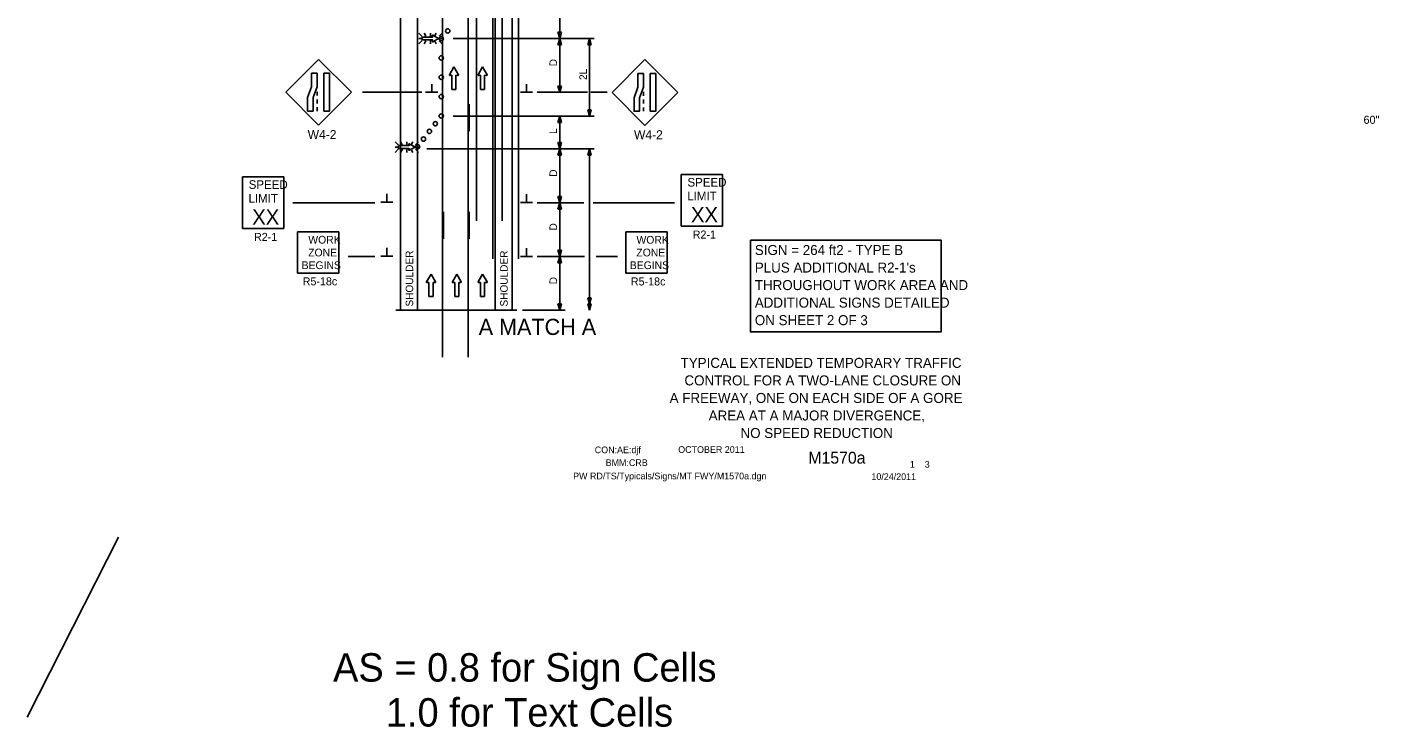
# Model space of a CAD drawing. Extents: x 16563 to 19504, y 6261 to 8279.
# Drawn here: x 16563 to 17820, y 6990 to 7640 of the extents above; entities that cross this region are included whole.
import ezdxf

# ---------------------------------------------------------------- set-up
doc = ezdxf.new("R2010")
doc.units = 0
for name, color, linetype in [('ALI_LEGAL_EX', 7, 'Continuous'), ('BORDER', 7, 'Continuous'), ('BORDER_SIGNAL_WO', 7, 'Continuous'), ('MT_SCRATCH_LEVEL_E', 7, 'Continuous'), ('PAVT_EDGE_EX', 7, 'Continuous'), ('TRAFFIC_SIGNS_PR', 7, 'Continuous'), ('TYPICAL_TEXT_DIMEN_EX', 7, 'Continuous'), ('TYPICAL_TEXT_DIMEN_PR', 7, 'Continuous')]:
    doc.layers.add(name, color=color, linetype=linetype)

msp = doc.modelspace()

# ---------------------------------------------------------------- linework, layer by layer
at = {"layer": 'ALI_LEGAL_EX'}
for p, q in [((16980.7, 8278.5), (16980.7, 7460.4)), ((17004.7, 8278.5), (17004.7, 7460.4)), ((16995.9, 8243.2), (16995.9, 7425)), ((17019.9, 8243.2), (17019.9, 7425)), ((16949, 7333.6), (16949, 7943.8)), ((16973, 7443.4), (16973, 7943.8)), ((16973, 7333.6), (16973, 7943.8)), ((16973, 7333.6), (16973, 7943.8))]:
    msp.add_line(p, q, dxfattribs=at)
for points in [[(16974, 7543.6), (16974, 7568.6)], [(16950, 7443.6), (16950, 7468.6)], [(16974, 7443.6), (16974, 7468.6)]]:
    msp.add_lwpolyline(points, dxfattribs=at)
at = {"layer": 'MT_SCRATCH_LEVEL_E'}
for p, q in [((16959.8, 7603.3), (16955.7, 7596)), ((16956.2, 7595.4), (16957.9, 7595.7)), ((16957.9, 7595.7), (16957.9, 7582.4)), ((16963.9, 7596), (16959.8, 7603.3)), ((16961.7, 7582.4), (16961.7, 7595.7)), ((16961.7, 7595.7), (16963.4, 7595.4)), ((16986.4, 7603.3), (16982.3, 7596)), ((16982.8, 7595.4), (16984.6, 7595.7)), ((16984.6, 7595.7), (16984.6, 7582.4)), ((16990.6, 7596), (16986.4, 7603.3)), ((16988.3, 7582.4), (16988.3, 7595.7)), ((16988.3, 7595.7), (16990.1, 7595.4)), ((16957.9, 7582.4), (16961.7, 7582.4)), ((16984.6, 7582.4), (16988.3, 7582.4)), ((16938.5, 7410.7), (16934.4, 7403.5)), ((16934.9, 7402.8), (16936.6, 7403.1)), ((16936.6, 7403.1), (16936.6, 7389.9)), ((16942.6, 7403.5), (16938.5, 7410.7)), ((16940.4, 7389.9), (16940.4, 7403.1)), ((16940.4, 7403.1), (16942.2, 7402.8)), ((16962.4, 7410.7), (16958.3, 7403.5)), ((16958.8, 7402.8), (16960.5, 7403.1)), ((16960.5, 7403.1), (16960.5, 7389.9)), ((16966.5, 7403.5), (16962.4, 7410.7)), ((16964.3, 7389.9), (16964.3, 7403.1)), ((16964.3, 7403.1), (16966.1, 7402.8)), ((16986.4, 7410.7), (16982.3, 7403.5)), ((16982.8, 7402.8), (16984.6, 7403.1)), ((16984.6, 7403.1), (16984.6, 7389.9)), ((16990.6, 7403.5), (16986.4, 7410.7)), ((16988.3, 7389.9), (16988.3, 7403.1)), ((16988.3, 7403.1), (16990.1, 7402.8)), ((16936.6, 7389.9), (16940.4, 7389.9)), ((16960.5, 7389.9), (16964.3, 7389.9)), ((16984.6, 7389.9), (16988.3, 7389.9))]:
    msp.add_line(p, q, dxfattribs=at)
for centre, start, end in [((16956.1, 7595.8), 150.4248, 279.9638), ((16963.5, 7595.8), 260.0362, 29.7731), ((16982.7, 7595.8), 150.4248, 279.9638), ((16990.2, 7595.8), 260.0362, 29.7731), ((16934.8, 7403.3), 150.4248, 279.9638), ((16942.2, 7403.3), 260.0362, 29.7731), ((16958.7, 7403.3), 150.4248, 279.9638), ((16966.1, 7403.3), 260.0362, 29.7731), ((16982.7, 7403.3), 150.4248, 279.9638), ((16990.2, 7403.3), 260.0362, 29.7731)]:
    msp.add_arc(centre, 0.463, start, end, dxfattribs=at)
at = {"layer": 'PAVT_EDGE_EX'}
for p, q in [((16910, 7753.8), (16910, 7377.1)), ((16926, 7753.8), (16926, 7377.1)), ((16998, 7753.8), (16998, 7377.1)), ((17014, 7753.8), (17014, 7377.1))]:
    msp.add_line(p, q, dxfattribs=at)
at = {"layer": 'TRAFFIC_SIGNS_PR'}
for p, q in [((16929.8, 7631.8), (16927, 7634.6)), ((16929.8, 7629.7), (16927, 7629.7)), ((16932.1, 7634.6), (16933.7, 7631.8)), ((16937.9, 7631.8), (16937.9, 7634.6)), ((16943.3, 7634.6), (16942.1, 7632.5)), ((16948.8, 7634.6), (16946, 7631.8)), ((16946, 7629.7), (16948.8, 7629.7)), ((16929.8, 7627.7), (16927, 7624.9)), ((16933.7, 7627.7), (16932.1, 7624.9)), ((16937.9, 7627.7), (16937.9, 7624.9)), ((16942.1, 7627.1), (16943.3, 7624.9)), ((16948.8, 7624.9), (16946, 7627.7)), ((16834, 7610.2), (16803.4, 7579.7)), ((16864.5, 7579.7), (16834, 7610.2)), ((17137.4, 7610.1), (17106.8, 7579.5)), ((17167.9, 7579.5), (17137.4, 7610.1)), ((16803.4, 7579.7), (16834, 7549.1)), ((16832.6, 7580.2), (16832.6, 7576.6)), ((16834, 7549.1), (16864.5, 7579.7)), ((17106.8, 7579.5), (17137.4, 7549)), ((17136, 7580.1), (17136, 7576.5)), ((17137.4, 7549), (17167.9, 7579.5)), ((16832.6, 7573), (16832.6, 7569.4)), ((17136, 7572.9), (17136, 7569.3)), ((16832.6, 7565.8), (16832.6, 7562.2)), ((17136, 7565.7), (17136, 7562.1)), ((16907.9, 7530.8), (16905.1, 7533.6)), ((16907.9, 7528.8), (16905.1, 7528.8)), ((16910.2, 7533.6), (16911.8, 7530.8)), ((16916, 7530.8), (16916, 7533.6)), ((16921.5, 7533.6), (16920.3, 7531.5)), ((16926.9, 7533.6), (16924.1, 7530.8)), ((16924.1, 7528.8), (16926.9, 7528.8)), ((16907.9, 7526.8), (16905.1, 7523.9)), ((16911.9, 7526.8), (16910.2, 7523.9)), ((16916, 7526.8), (16916, 7523.9)), ((16920.2, 7526.1), (16921.5, 7523.9)), ((16926.9, 7523.9), (16924.1, 7526.8)), ((16763.2, 7501.1), (16801.6, 7501.1)), ((16763.2, 7453.1), (16763.2, 7501.1)), ((16801.6, 7453.1), (16801.6, 7501.1)), ((17171.1, 7503.2), (17209.5, 7503.2)), ((17171.1, 7455.2), (17171.1, 7503.2)), ((17209.5, 7455.2), (17209.5, 7503.2)), ((17171.1, 7455.2), (17209.5, 7455.2)), ((16763.2, 7453.1), (16801.6, 7453.1)), ((16814.4, 7411.7), (16814.4, 7450.1)), ((16814.4, 7450.1), (16852.8, 7450.1)), ((16852.8, 7411.7), (16852.8, 7450.1)), ((17119.5, 7411.6), (17119.5, 7450)), ((17119.5, 7450), (17157.9, 7450)), ((17157.9, 7411.6), (17157.9, 7450)), ((16814.4, 7411.7), (16852.8, 7411.7)), ((17119.5, 7411.6), (17157.9, 7411.6))]:
    msp.add_line(p, q, dxfattribs=at)
for points in [[(16939.7, 7632.4), (16939.9, 7631.1), (16930.2, 7631.1), (16930.2, 7628.4), (16939.9, 7628.4), (16939.7, 7627.1)], [(16940.2, 7626.7), (16945.5, 7629.7), (16940.2, 7632.8)], [(16917.8, 7531.5), (16918.1, 7530.2), (16908.3, 7530.2), (16908.3, 7527.4), (16918.1, 7527.4), (16917.8, 7526.1)], [(16918.3, 7525.8), (16923.6, 7528.8), (16918.3, 7531.8)]]:
    msp.add_lwpolyline(points, dxfattribs=at)
for points in [[(16832.6, 7597.4), (16832.6, 7584.8), (16828.8, 7574.8), (16828.8, 7562.2), (16823.7, 7562.2), (16823.7, 7574.8), (16827.5, 7584.8), (16827.5, 7597.4)], [(16844, 7597.4), (16844, 7562.2), (16838.9, 7562.2), (16838.9, 7597.4)], [(17136, 7597.2), (17136, 7584.6), (17132.2, 7574.6), (17132.2, 7562.1), (17127.2, 7562.1), (17127.2, 7574.6), (17130.9, 7584.6), (17130.9, 7597.2)], [(17147.4, 7597.2), (17147.4, 7562.1), (17142.3, 7562.1), (17142.3, 7597.2)]]:
    msp.add_lwpolyline(points, close=True, dxfattribs=at)
for centre in [(16948, 7629.7), (16954, 7636.8), (16948, 7611.7), (16948, 7593.7), (16948, 7575.7), (16948, 7557.7), (16937, 7543.4), (16942.5, 7550.5), (16926, 7529.2), (16931.5, 7536.3)]:
    msp.add_circle(centre, 2, dxfattribs=at)
for centre, start, end in [((16940, 7632.5), 61.4833, 189.9593), ((16940, 7627), 170.7308, 298.8916), ((16918.2, 7531.5), 61.4833, 189.9593), ((16918.2, 7526.1), 170.7308, 298.8916)]:
    msp.add_arc(centre, 0.341, start, end, dxfattribs=at)
at = {"layer": 'TYPICAL_TEXT_DIMEN_EX'}
msp.add_lwpolyline([(17235.4, 7442.4), (17412.7, 7442.4), (17412.7, 7357.1), (17235.4, 7357.1)], close=True, dxfattribs=at)
at = {"layer": 'TYPICAL_TEXT_DIMEN_PR'}
for p, q in [((17058.1, 7629.7), (17058.1, 7658.2)), ((17090.2, 7629.7), (16959, 7629.7)), ((17058.1, 7629.7), (17056.5, 7635.5)), ((17056.5, 7635.5), (17058.1, 7635.5)), ((17056.5, 7623.8), (17058.1, 7629.7)), ((17058.1, 7635.5), (17059.7, 7635.5)), ((17059.7, 7635.5), (17058.1, 7629.7)), ((17058.1, 7629.7), (17058.1, 7579.7)), ((17058.1, 7629.7), (17059.7, 7623.8)), ((17084.4, 7623.8), (17085.9, 7629.7)), ((17085.9, 7629.7), (17087.5, 7623.8)), ((17085.9, 7629.7), (17085.9, 7557.7)), ((17058.1, 7623.8), (17056.5, 7623.8)), ((17059.7, 7623.8), (17058.1, 7623.8)), ((17085.9, 7623.8), (17084.4, 7623.8)), ((17087.5, 7623.8), (17085.9, 7623.8)), ((16874.8, 7579.7), (16930, 7579.7)), ((16944.8, 7579.7), (16933.5, 7579.7)), ((16939.2, 7579.7), (16939.2, 7587.4)), ((17032.9, 7579.7), (17021.6, 7579.7)), ((17027.2, 7579.7), (17027.2, 7587.4)), ((17083.9, 7579.7), (17037.1, 7579.7)), ((17058.1, 7579.7), (17056.5, 7585.5)), ((17056.5, 7585.5), (17058.1, 7585.5)), ((17058.1, 7585.5), (17059.7, 7585.5)), ((17059.7, 7585.5), (17058.1, 7579.7)), ((17102.1, 7579.7), (17087.1, 7579.7)), ((16959, 7557.7), (17090.2, 7557.7)), ((17056.5, 7551.8), (17058.1, 7557.7)), ((17058.1, 7527.1), (17058.1, 7557.7)), ((17058.1, 7557.7), (17059.7, 7551.8)), ((17085.9, 7557.7), (17084.4, 7563.5)), ((17084.4, 7563.5), (17085.9, 7563.5)), ((17085.9, 7563.5), (17087.5, 7563.5)), ((17087.5, 7563.5), (17085.9, 7557.7)), ((17058.1, 7551.8), (17056.5, 7551.8)), ((17059.7, 7551.8), (17058.1, 7551.8)), ((17058.1, 7527.1), (17056.5, 7533)), ((17056.5, 7533), (17058.1, 7533)), ((17058.1, 7533), (17059.7, 7533)), ((17059.7, 7533), (17058.1, 7527.1)), ((16934.5, 7527.1), (17090.2, 7527.1)), ((17056.5, 7521.2), (17058.1, 7527.1)), ((17058.1, 7521.2), (17056.5, 7521.2)), ((17058.1, 7527.1), (17058.1, 7477.1)), ((17058.1, 7527.1), (17059.7, 7521.2)), ((17059.7, 7521.2), (17058.1, 7521.2)), ((17084.4, 7521.2), (17085.9, 7527.1)), ((17084.4, 7521.2), (17085.9, 7527.1)), ((17085.9, 7521.2), (17084.4, 7521.2)), ((17085.9, 7521.2), (17084.4, 7521.2)), ((17085.9, 7527.1), (17085.9, 7377.1)), ((17085.9, 7527.1), (17087.5, 7521.2)), ((17085.9, 7527.1), (17087.5, 7521.2)), ((17087.5, 7521.2), (17085.9, 7521.2)), ((17087.5, 7521.2), (17085.9, 7521.2)), ((16897.4, 7477.5), (16897.4, 7485.3)), ((17027.2, 7477.2), (17027.2, 7485)), ((17058.1, 7477.1), (17056.5, 7483)), ((17056.5, 7483), (17058.1, 7483)), ((17058.1, 7483), (17059.7, 7483)), ((17059.7, 7483), (17058.1, 7477.1)), ((16809.9, 7477.1), (16886.3, 7477.1)), ((16903, 7477.5), (16891.8, 7477.5)), ((17032.9, 7477.2), (17021.6, 7477.2)), ((17037.1, 7477.1), (17080.7, 7477.1)), ((17056.5, 7471.2), (17058.1, 7477.1)), ((17058.1, 7471.2), (17056.5, 7471.2)), ((17058.1, 7477.1), (17058.1, 7427.1)), ((17058.1, 7477.1), (17059.7, 7471.2)), ((17059.7, 7471.2), (17058.1, 7471.2)), ((17089.3, 7477.1), (17164.8, 7477.1)), ((16897.4, 7427.5), (16897.4, 7435.3)), ((17027.2, 7427.2), (17027.2, 7435)), ((17058.1, 7427.1), (17056.5, 7433)), ((17056.5, 7433), (17058.1, 7433)), ((17058.1, 7433), (17059.7, 7433)), ((17059.7, 7433), (17058.1, 7427.1)), ((16861.4, 7427.1), (16886.3, 7427.1)), ((16903, 7427.5), (16891.8, 7427.5)), ((17032.9, 7427.2), (17021.6, 7427.2)), ((17037.1, 7427.1), (17081.1, 7427.1)), ((17056.5, 7421.2), (17058.1, 7427.1)), ((17058.1, 7421.2), (17056.5, 7421.2)), ((17058.1, 7427.1), (17058.1, 7377.1)), ((17058.1, 7427.1), (17059.7, 7421.2)), ((17059.7, 7421.2), (17058.1, 7421.2)), ((17092, 7427.1), (17111.9, 7427.1)), ((17058.1, 7377.1), (17056.5, 7383)), ((17056.5, 7383), (17058.1, 7383)), ((17058.1, 7383), (17059.7, 7383)), ((17059.7, 7383), (17058.1, 7377.1)), ((17085.9, 7382.9), (17084.4, 7388.7)), ((17084.4, 7388.7), (17085.9, 7388.7)), ((17085.9, 7377.1), (17084.4, 7383)), ((17084.4, 7383), (17085.9, 7383)), ((17085.9, 7388.7), (17087.5, 7388.7)), ((17087.5, 7388.7), (17085.9, 7382.9)), ((17085.9, 7383), (17087.5, 7383)), ((17087.5, 7383), (17085.9, 7377.1)), ((16905.7, 7377.1), (17018.3, 7377.1)), ((17023.5, 7377.1), (17063.1, 7377.1)), ((16647.8, 7166.2), (16562.9, 6998.9))]:
    msp.add_line(p, q, dxfattribs=at)

# ---------------------------------------------------------------- texts
at = {"layer": 'BORDER'}
for s, p in [('TYPICAL EXTENDED TEMPORARY TRAFFIC', (17170.5, 7323.6)), ('CONTROL FOR A TWO-LANE CLOSURE ON', (17174.1, 7307.3)), ('A FREEWAY, ONE ON EACH SIDE OF A GORE', (17160.3, 7291)), ('AREA AT A MAJOR DIVERGENCE,', (17196.6, 7274.7)), ('NO SPEED REDUCTION', (17226.2, 7258.4))]:
    msp.add_text(s, height=9.3, dxfattribs=at).set_placement(p)
at = {"layer": 'BORDER_SIGNAL_WO'}
for s, height, p in [('CON:AE:djf  ', 6.2, (17090.7, 7244.3)), ('    OCTOBER 2011    ', 6.2, (17159.1, 7244.6)), ('    M1570a   ', 11, (17272.9, 7234.6)), ('BMM:CRB   ', 6.2, (17100.8, 7232.4)), (' 1    3 ', 6.2, (17381.4, 7230.9)), ('PW RD/TS/Typicals/Signs/MT FWY/M1570a.dgn      ', 6.2, (17070.6, 7220)), ('10/24/2011    ', 6.2, (17347.9, 7219.4)), ('AS = 0.8 for Sign Cells', 26.424, (16847.4, 7032)), ('     1.0 for Text Cells', 26.424, (16847.4, 6990.2))]:
    msp.add_text(s, height=height, dxfattribs=at).set_placement(p)
at = {"layer": 'TRAFFIC_SIGNS_PR'}
for s, height, p in [('W4-2', 8.37, (16823.8, 7536.3)), ('W4-2', 8.37, (17127.2, 7536.1)), ('SPEED', 8, (16769, 7490)), ('SPEED', 8, (17176.9, 7492.1)), ('LIMIT', 8, (16768.8, 7477.2)), ('LIMIT', 8, (17176.7, 7479.3)), ('XX', 14.03, (16772.3, 7456.8)), ('XX', 14.03, (17180.2, 7459)), ('R2-1', 7.44, (16773.9, 7441.6)), ('WORK', 7.22, (16824.4, 7439.1)), ('WORK', 7.22, (17129.5, 7439)), ('R2-1', 7.44, (17181.8, 7443.8)), ('ZONE', 7.22, (16824.3, 7427.2)), ('ZONE', 7.22, (17129.4, 7427.2)), ('BEGINS', 7.22, (16818.2, 7415.4)), ('BEGINS', 7.22, (17123.3, 7415.4)), ('R5-18c', 7.44, (16819.2, 7400.3)), ('R5-18c', 7.44, (17124.3, 7400.2))]:
    msp.add_text(s, height=height, dxfattribs=at).set_placement(p)
at = {"layer": 'TYPICAL_TEXT_DIMEN_EX'}
for s, p in [('SIGN = 264 ft2 - TYPE B', (17239.5, 7428.5)), ("PLUS ADDITIONAL R2-1's", (17239.5, 7412.2)), ('THROUGHOUT WORK AREA AND', (17239.5, 7395.9)), ('ADDITIONAL SIGNS DETAILED', (17239.5, 7379.6)), ('ON SHEET 2 OF 3', (17239.5, 7363.3))]:
    msp.add_text(s, height=9.3, dxfattribs=at).set_placement(p)
at = {"layer": 'TYPICAL_TEXT_DIMEN_PR'}
for s, p in [('D', (17055.6, 7603.9)), ('2L', (17083.4, 7591.2)), ('L', (17055.6, 7541)), ('D', (17055.6, 7501.3)), ('D', (17055.6, 7451.3)), ('SHOULDER', (16921.9, 7380.6)), ('SHOULDER', (17009.8, 7380.6)), ('D', (17055.6, 7401.3))]:
    msp.add_text(s, height=7, rotation=90, dxfattribs=at).set_placement(p)
for s, height, p in [('60"', 7.55, (17805.4, 7550.4)), ('A MATCH A', 15, (16982.8, 7354.2))]:
    msp.add_text(s, height=height, dxfattribs=at).set_placement(p)

doc.saveas('drawing.dxf')
